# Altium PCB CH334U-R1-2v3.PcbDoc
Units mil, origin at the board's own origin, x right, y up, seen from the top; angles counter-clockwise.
Board outline 3110.24 x 866.14 mil, 2 copper layers (Top Layer, Bottom Layer); 19 components, 20 nets, 108 pads, 280 vias.
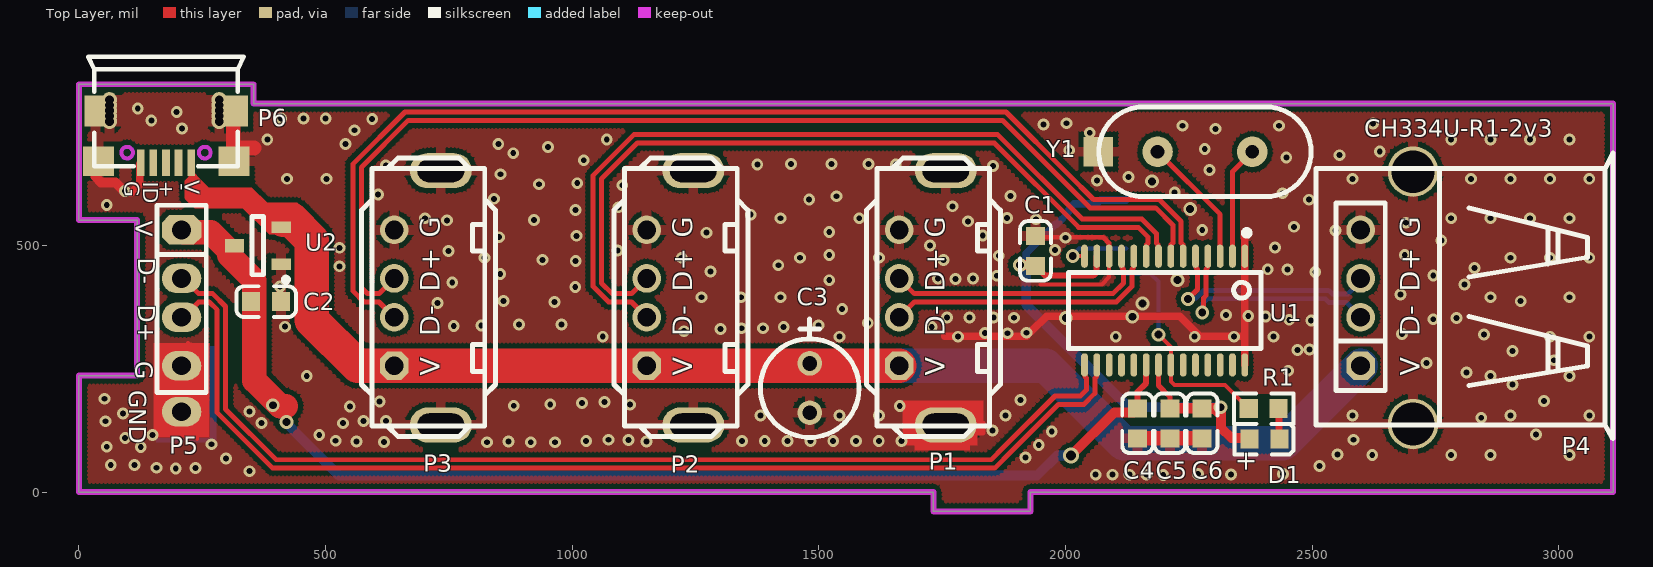
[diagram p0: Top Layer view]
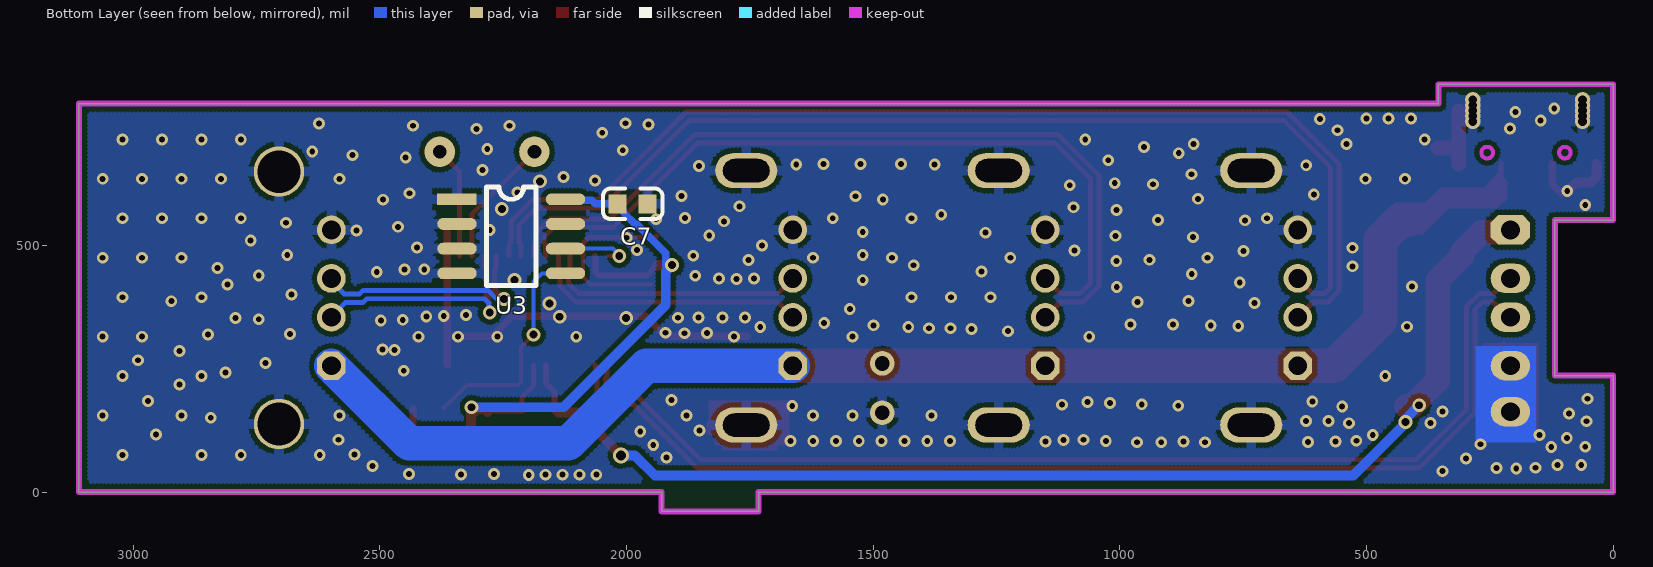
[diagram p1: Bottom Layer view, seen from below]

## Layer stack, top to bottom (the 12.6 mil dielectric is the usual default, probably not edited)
Top Solder: solder mask 0.4, Solder Resist, Dk 3.5
Top Layer: signal copper 1.4
Dielectric 1: dielectric 12.6, FR-4, Dk 4.8
Bottom Layer: signal copper 1.4
Bottom Solder: solder mask 0.4, Solder Resist, Dk 3.5

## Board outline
0,0 0,236.22 118.11,236.22 118.11,551.18 0,551.18 0,826.77 354.33,826.77 354.33,787.4 3110.24,787.4 3110.24,0 1929.13,0 1929.13,-39.37 1732.28,-39.37 1732.28,0

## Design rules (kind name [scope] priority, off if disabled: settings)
Clearance Clearance_1 [InPolygon] p1: gap=10 ignorepadtopadclearanceinfootprint=FALSE
Clearance [All] p2: gap=6 ignorepadtopadclearanceinfootprint=FALSE except(8: Arc-Via Track-Via SMDPad-Via THPad-Via Via-Via Via-Fill Via-Poly Via-Region Via-Hole)
ComponentClearance [All] p1 off: gap=10 collisioncheckmode=3 verticalgap=10 showdistances=FALSE
DiffPairsRouting [All] p1: maxlimit=10 minlimit=7 mostfreqgap=8 toplayer_minwidth=6 toplayer_maxwidth=15 toplayer_prefwidth=8 bottomlayer_minwidth=6 bottomlayer_maxwidth=15 bottomlayer_prefwidth=8 maxuncoupledlength=500
MinimumSolderMaskSliver [All] p1 off: minsoldermaskwidth=10
PolygonConnect PolygonConnect_1 [IsVia] p1: connectstyle=Direct reliefconductorwidth=10 reliefentries=4 polygonreliefangle="90 Angle" airgapwidth=10
PolygonConnect [All] p2: connectstyle=Relief reliefconductorwidth=20 reliefentries=4 polygonreliefangle="90 Angle" airgapwidth=10
RoutingVias [All] p1: holewidth=16 width=28 viastyle="Through Hole" minholewidth=12 minwidth=24 maxholewidth=28 maxwidth=50
SilkToSilkClearance [All] p1 off: silktosilkclearance=10
SilkToSolderMaskClearance [IsPad] p1 off: minsilkscreentomaskgap=10 clearancetoexposedcopper=TRUE
SolderMaskExpansion [All] p1: expansion=4 istentingtop=FALSE
Width [All] p1: maxlimit=100 minlimit=6 preferedwidth=10
25 further rules are at their usual default settings.

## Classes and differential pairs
differential pair UD: +UD_p -UD_n
differential pair UD4: +UD4_p -UD4_n
differential pair UD3: +UD3_p -UD3_n
differential pair UD2: +UD2_p -UD2_n
differential pair UD1: +UD1_p -UD1_n

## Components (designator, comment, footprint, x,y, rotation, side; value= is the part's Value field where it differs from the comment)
C1 "1uF" 0603_C 1939.33,458.56 r90 top
C2 "10uF" 0603_C 349.31,386.02 r0 top
C3 "220uF" CD0.1 1481.53,260.82 r270 top
C4 "1uF" 0603_C 2146.15,169.64 r270 top
C5 "0.1uF" 0603_C 2211.63,169.64 r270 top
C6 "10uF" 0603_C 2277.11,169.64 r270 top
C7 "NC(1uF)" 0603_C 2017.91,584.37 r180 bottom
D1 "LED" 0603+ 2372.9,107.41 r0 top
P1 "USB" USB2.0-A-F-TH_4P-V_13.7mm 1662.83,255.91 r180 top
P2 "USB" USB2.0-A-F-TH_4P-V_13.7mm 1151.02,255.91 r180 top
P3 "USB" USB2.0-A-F-TH_4P-V_13.7mm 639.21,255.91 r180 top
P4 "USB" USBAF#1 2598.25,255.91 r90 top
P5 "USB" USBAF#2 208.21,531.5 r270 top
P6 "PowerSupply" USBMICROB-02-GXPX-A1T2 227.66,667.45 r180 top
R1 "1K" 0603_R 2401.83,169.06 r0 top
U1 "CH334U" QSOP28 2363.63,478.14 r180 top
U2 "CH213K" SOT-23-3 409.9,462.15 r90 top
U3 "NC(24C02)" SOIC-8_150mil 2343.8,593.5 r270 bottom
Y1 "12M" XT_AT49 2186.69,689.86 r270 top

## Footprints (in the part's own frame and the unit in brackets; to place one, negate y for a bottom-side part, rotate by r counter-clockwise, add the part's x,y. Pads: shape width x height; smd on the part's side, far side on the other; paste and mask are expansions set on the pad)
0603+ [mm]
  rect 0.93x0.98 smd: 1(0,0) 2(1.54,0)
  silkscreen extent -0.76,-0.79 2.27,0.79
0603_C [mm]
  rect 0.93x0.98 smd: 1(0,0) 2(1.54,0)
  silkscreen extent -0.76,-0.79 2.31,0.79
0603_R [mm]
  rect 0.93x0.98 smd: 1(-0.77,0) 2(0.77,0)
  silkscreen extent -1.53,-0.79 1.54,0.79
CD0.1 [mil]
  round 50 hole 30: 1(0,0) 2(100,0)
  silkscreen extent -90,-100 150,100
QSOP28 [mm]
  oval 0.35x1.2 smd mask+0.051: 1(0,0) 2(0.635,0) 3(1.27,0) 4(1.905,0) 5(2.54,0) 6(3.175,0) 7(3.81,0) 8(4.445,0) 9(5.08,0) 10(5.715,0) 11(6.35,0) 12(6.985,0) 13(7.62,0) 14(8.255,0) 15(8.255,5.6) 16(7.62,5.6) 17(6.985,5.6) 18(6.35,5.6) 19(5.715,5.6) 20(5.08,5.6) 21(4.445,5.6) 22(3.81,5.6) 23(3.175,5.6) 24(2.54,5.6) 25(1.905,5.6) 26(1.27,5.6) 27(0.635,5.6) 28(0,5.6)
  silkscreen extent -0.82,-1.35 9.08,4.75
SOIC-8_150mil [mil]
  rect 24x80 smd: 1(0,0)
  oval 24x80 smd: 2(50,0) 3(100,0) 4(150,0) 5(150,220) 6(100,220) 7(50,220) 8(0,220)
  silkscreen extent -25,60 175,160
SOT-23-3 [mm] "SOT-23-3"
  rect 0.6x1 smd: 1(0,0) 2(1.9,0)
  rect 0.7x1 smd: 3(0.95,2.4)
  silkscreen extent -0.93,-0.38 2.45,1.49
USB2.0-A-F-TH_4P-V_13.7mm [mm]
  oval 3.2x1.8 hole 1.2 slot 2.4 at 0 deg: 0(-2.4,3.05) 0(-2.4,-10.05)
  oct 1.473x1.473 hole 0.965: 1(0,0)
  round 1.473 hole 0.965: 2(0,-2.5) 3(0,-4.5) 4(0,-7)
  silkscreen extent -5.21,-10.71 1.69,3.65
USBAF#1 [mm]
  round 2.6 hole 2.2: 0(-3,-2.7) 0(10,-2.7)
  oct 1.473x1.473 hole 0.965: 1(0,0)
  round 1.473 hole 0.965: 2(2.5,0) 3(4.5,0) 4(7,0)
  silkscreen extent -3.75,-12.99 10.95,2.29
USBAF#2 [mm]
  oct 1.524x2.032 hole 0.965: 1(0,0)
  oval 1.524x2.032 hole 0.965: 2(2.5,0) 3(4.5,0) 4(7,0)
  silkscreen extent -1.27,-1.27 8.38,1.27
USBMICROB-02-GXPX-A1T2 [mm]
  rect 1.6x1.5 smd: 0(-2.203,-0.083) 0(4.769,-0.083)
  rect 1.5x1.6 smd: 0(-2.167,-2.675)
  round 0.8 hole 0.45: 0(-1.442,-2.134) 0(-1.442,-3.243) 0(-1.442,-2.966) 0(-1.442,-2.689) 0(-1.442,-2.411) 0(4.208,-2.689) 0(4.208,-2.411) 0(4.208,-2.134) 0(4.208,-3.243) 0(4.208,-2.966)
  rect 1.1x1.6 smd: 0(4.933,-2.675)
  rect 0.4x1.35 smd mask+0.051: 1(0,0) 2(0.65,0) 3(1.3,0) 4(1.95,0) 5(2.6,0)
  Keep-Out Layer circle w0.203: c3.3,-0.525 r0.3
  Keep-Out Layer circle w0.203: c-0.7,-0.525 r0.3
  silkscreen extent -2.7,-5.46 5.3,0.17
XT_AT49 [mil]
  rect 60x60 smd: 0(0.03,-119.99)
  round 62 hole 28: 1(0,0) 2(0,192.13)
  silkscreen extent -91,-119 91,311

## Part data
C1 C2 C3 C4 C5 C6 C7: library part CAP, "Capacitor"
D1: "Typical INFRARED GaAs LED"
P1 P2 P3 P4 P5: "USB Port"
P6: library part MicroUSB, "MicroUSB Port"
R1: library part RES
U1: "4 ports High-Speed USB MTT Hub with over current detect & power control"
U2: "Ideal Diode 5V*1A"
U3: library part 24C01
Y1: library part XTAL, "Crystal Oscillator"

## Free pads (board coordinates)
  oval 80x60 hole 38: ""(208.21,162.81)

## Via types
v1: diameter 24, hole 12, Top Layer to Bottom Layer, tented both sides, 265 vias
v2: diameter 28, hole 16, Top Layer to Bottom Layer, tented both sides, 14 vias
v3: diameter 32, hole 20, Top Layer to Bottom Layer, tented both sides, 1 vias

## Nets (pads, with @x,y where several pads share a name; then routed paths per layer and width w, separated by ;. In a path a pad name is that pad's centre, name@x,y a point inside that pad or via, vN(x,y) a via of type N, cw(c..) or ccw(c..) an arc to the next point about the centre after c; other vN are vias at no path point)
3V3: C1.1 C5.1 C6.1 C7.1 D1.1 U1.13 U1.21 U3.8 | length 1479.1
  Top Layer w10: U1.21 2188.63,216.02 2211.63,193.02 C5.1
  Top Layer w12: C1.1 1959.24,438.65 2056.26,438.65 2063.29,445.68 2063.29,477.8 U1.13
  Top Layer w20: v2(1907.71,460.4) 1937.5,460.4 C1.1 ; C6.1 C5.1 2212.82,170.83 2312.93,170.83 v2(2314.13,172.03) ; C6.1@2282.24,162.58 2282.24,164.22 2286.4,168.38 2302.53,168.38 2315.66,155.26 ; v2@2313.15,170.83 2315.66,168.33 2315.66,155.26 ; D1.1 2371.07,109.24 2336.31,109.24 2315.66,129.89 2315.66,155.26
  Bottom Layer w10: C7.1@2016.85,583.32 C7.1
  Bottom Layer w15: v2(1907.71,460.4) 1907.71,463.92 v2@1910.19,466.4 ; 1920.6,447.51 1920.6,484.38 1979.23,543.01 1982.39,543.01 2007.1,567.72 2007.1,573.57 C7.1@2016.85,583.32 ; C7.1 2063.35,584.37 2070.76,591.78 2122.08,591.78 U3.8
  Bottom Layer w20: v2(1907.71,460.4) 1920.6,447.51 1920.6,379.07 2127.64,172.03 v2(2314.13,172.03)
5V: C2.1 C4.1 P5.1 U1.20 U2.3 | length 2482
  Top Layer w12: C4.1 2146.15,170.45 2146.15,203.34 2163.63,220.82 U1.20
  Top Layer w20: v2(420.75,142.21) 421.85,143.31 421.85,169.48 422.95,170.59 ; v3(2011.47,73.96) 2098.85,161.34 2137.84,161.34 C4.1
  Top Layer w50: P5.1 212.86,526.85 267.14,526.85 304.93,489.07 304.93,479.82 355.63,429.12 355.63,226.31 407.93,174.01 419.54,174.01
  Bottom Layer w20: v2(393.17,176.02) 420.75,148.44 v2(420.75,142.21) 420.75,139.49 526.89,33.35 1942.64,33.35 1983.25,73.96 v3(2011.47,73.96)
GND: C1.2 C2.2 C3.2 C4.2 C5.2 C6.2 C7.2 P1.0 P1.4 P2.0 P2.4 P3.0 P3.4 P4.0 P4.4 P5.4 P6.0 P6.5 pad. U1.1 U1.12 U1.28 U2.1 U3.1 U3.2 U3.3 U3.4 U3.7 Y1.0 | length 2598.1
  Top Layer w8: 220.81,208.41 220.81,302.53 ; 222,112.53 222,206.65 ; 225,112.53 225,206.65 ; 227.09,204.87 227.09,299 ; 230,111.08 230,205.21 ; 233,204.17 233,298.3 ; 234,111.08 234,205.21 ; 240,107.99 240,295.21 ; 1834.11,119.74 1834.11,140.29 ; 1949.47,421.2 2073.92,421.2 2088.63,435.91 U1.12
  Top Layer w10: C1.2 1941.99,516.54 1998.9,516.54 v1(1999.92,515.51) ; v1@1999.92,516.54 2076.28,516.54 2087.91,504.91 2087.91,478.87 U1.12
  Top Layer w15: 104.84,605.5 123.71,624.36 P6.5@123.71,665.85 ; 1755.16,316.05 1837.22,316.05 1882.4,316.05 v1@1921.37,316.05 ; v1@1921.37,318.73 1921.37,320.45 1925.53,324.61 1929.93,324.61 1961.78,356.46 2231.88,356.46 2272.29,316.05 2363.63,316.05 ; U1.28 2363.63,316.05 ; 2363.63,525.85 U1.1 2363.63,356.8 2363.63,316.05
  Top Layer w20: P6.0@33.46,665 33.46,639.41 45.12,627.76 74.35,627.76 91.94,610.17 v1(93.02,610.17)
  Top Layer w30: P6.0@312.99,665 P6.0@312.99,682.72 ; P6.0@312.99,772.76 P6.0@312.99,682.72 ; 354.76,697.24 327.52,697.24 P6.0@312.99,682.72 ; C4.2 C5.2 C6.2
  other v1: 2061.33,35.21 2095.56,35.21 2129.78,35.21 2164,35.21 2198.23,34.79 2268.68,36.44 2335.68,35.87 2441,36.54 345.77,42.29 196.36,47.86 157.58,49.29 236.59,48.81 2514.7,52.91 64.67,55.04 112.56,54.56 298,68.06 1919.06,69.76 2622,75 2782,75 2862,75 3022,75 2551.51,75.81 125.49,91.43 56.53,91.91 1945.85,95.33 269.09,96.97 618.87,101.5 827.57,100.97 916.07,100.97 965.42,100.97 563.05,102.8 870.97,102.68 1150.93,102.68 1344.12,103.19 1390.38,103.19 1436.63,103.19 1482.89,103.19 1529.14,103.19 1575.4,103.19 1621.65,103.19 1667.91,103.19 520.64,104.1 1028.39,103.53 1114.34,105.23 1073.49,106.08 2584.23,106.08 93.89,109.63 149.43,115.38 487.31,115.35 2953.66,116.98 1972.29,122.48 1852.19,124.57 370.18,139.83 535.35,139.58 54.14,143.63 576.89,143.91 622.77,143.91 2842.89,150.73 1382,155 1542,155 1622,155 1878.22,155.1 2582,155 2902,155 3062,155 89.58,159.43 345.61,163.53 549.2,173.34 1664.05,174.13 881.63,174.96 1117.55,177.16 955.63,177.89 1020.11,180.82 1065.53,182.28 609.78,183.72 2970.04,184.47 1909.19,186.51 51.74,189.12 2906.47,218.22 462,235 2862,235 3022,235 2813.04,242.58 2451.62,245.94 2732.05,261.79 2990.27,267.24 2906.47,285.71 2470.56,288.06 2494.58,288.9 1062,315 1542,315 1782,315 2102,315 2262,315 2342,315 2422,315 2982,315 3062,315 2848.67,319.45 2681.97,320.55 1837.22,322.36 1882.4,321.92 1921.37,322.89 1226.76,326.1 1300.83,330.59 1343.48,332.09 1386.87,332.09 1428.77,334.33 1729.02,334.29 417.75,335.28 760.01,336.88 815.69,337.61 1499.1,338.07 891.89,339.81 978.34,339.81 1599.31,342.91 2498.14,347.64 2453.7,349.18 2745.54,350.41 1895.47,353.41 2792.74,353.2 1759.58,353.55 1805.52,353.88 1854.11,354.21 2405.89,356.11 2370.55,356.8 2325.61,359.04 1547.41,370.82 727.04,383.04 964.42,385.23 861.12,387.43 2922.84,386.94 1262,395 1342,395 1422,395 2862,395 3022,395 2679.08,400.49 1006.25,415.39 407.69,416.39 2809.11,420.69 756.97,424.97 1521.18,429.51 1776.76,432.22 1741.73,433.21 1812.79,433.21 1860.72,438.5 2745.54,439.02 854.15,442.07 2506.38,445.9 1280.14,447.3 2449.96,450.97 2410.03,451.6 2829.34,454.43 528.28,457.62 1417.86,459.82 1007.16,468.13 1752.63,470.43 939.67,470.84 822,475 1222,475 1462,475 1622,475 2902,475 2982,475 3062,475 1864.76,479.09 2687.75,480.44 1521.18,480.68 749.2,488.72 1092.03,489.51 1978.53,490.41 528.28,495.19 2424.77,495.93 1725.48,499.88 2761.91,510.3 851.82,516.71 1009,519.49 1832.29,520.21 1272.17,525.84 1521.18,527.32 2547.29,530.47 2277.37,531.17 2463.48,537.76 2690.64,545.94 1802.57,548.85 746.09,550.91 922.56,551.69 1940.47,553.02 702,555 1422,555 1582,555 1881.66,555.45 2782,555 2862,555 2942,555 3022,555 1362.09,562.26 1006.71,571.47 1093.71,577.24 1770.67,579.29 56.52,582.14 1480.46,592.99 2493.44,592.7 841.71,594.45 1535.62,599.64 1888.37,600.38 606.78,603.49 2439.65,605.79 2221.41,607.65 1101.53,621.94 932.67,623.99 1010.25,626.12 2064.1,631.9 422,635 502,635 2582,635 2822,635 2902,635 2982,635 3062,635 2127.52,638.74 854.93,644.21 2291.67,653.04 1852.78,660.76 622.24,662.42 1375.3,663.89 1655.97,663.89 1443.81,664.72 1525.54,664.72 1600.66,664.72 1023.41,672.66 2447.74,677.92 2555.52,682.93 880.58,686.96 2637.09,690.68 2007.76,692.99 2282.34,695.33 951.33,699.4 540.34,705.78 850.26,705.62 382,715 1070.19,714.85 2782,715 2862,715 2942,715 3022,715 2049.23,728.4 559.03,733.42 2304.1,736.36 209.17,737.14 2237.57,742.58 2432.81,742.58 1955.73,745.02 2623.79,747.43 2001.86,747.7 146.87,753.14 594.56,756.21 409.91,757.18 455.11,757.18 500.31,757.18 198.29,770.28 119.32,777.75
  other v2: 2000.78,352.78 2135.57,355.3 2156.25,382.45 2227.08,429.89 2252.85,574.13 2175.55,629.96
NetD1_2: D1.2 R1.2 | length 62.2
  Top Layer w15: R1.2 2432.84,168.37 2432.84,108.1 D1.2
NetU1_2: U1.2 Y1.2 | length 228.4
  Top Layer w10: U1.2 2338.63,649.68 Y1.2
NetU1_3: U1.3 Y1.1 | length 264.3
  Top Layer w10: Y1.1 2313.63,562.92 U1.3
RST: U1.17
SCL: U1.14 U3.6 | length 140.6
  Top Layer w8: v2(2014.88,478.5) 2038.27,478.5 U1.14
  Bottom Layer w8: v2(2014.88,478.5) 2014.88,481.18 2027.2,493.5 U3.6
SDA: R1.1 U1.22 U3.5 | length 466
  Top Layer w8: v2(2188.34,319.06) 2213.63,293.77 U1.22 2213.63,223.9 2220.64,216.89 2323.68,216.89 2356.23,184.35 2357.21,184.35 2371.52,170.04 R1.1
  Bottom Layer w8: U3.5 2171.64,443.5 2188.34,426.8 v2(2188.34,319.06)
UD1_n: P1.2 U1.10 | length 560.8
  Top Layer w10: P1.2 1693.7,385.2 2103.23,385.2 2134.63,416.6 2134.63,451.45 2137.91,454.73 2137.91,477.42 U1.10
UD1_p: P1.3 U1.11 | length 532.6
  Top Layer w10: P1.3 1693.7,402.2 2096.19,402.2 2117.63,423.64 2117.63,451.45 2114.35,454.73 2114.35,477.42 U1.11
UD2_n: P2.2 U1.8 | length 1666.8
  Top Layer w10: P2.2 1120.15,385.2 1073.88,385.2 1042.46,416.62 1042.46,642.09 1125.07,724.7 1862.77,724.7 2033.79,553.67 2154.76,553.67 2184.63,523.81 2184.63,504.83 2187.91,501.55 2187.91,478.87 U1.8
UD2_p: P2.3 U1.9 | length 1582.3
  Top Layer w10: P2.3 1120.15,402.2 1080.92,402.2 1059.46,423.67 1059.46,635.05 1132.11,707.7 1855.72,707.7 2026.75,536.67 2147.72,536.67 2167.63,516.76 2167.63,504.83 2164.35,501.55 2164.35,478.87 U1.9
UD3_n: P3.2 U1.6 | length 2249.5
  Top Layer w10: P3.2 608.34,385.2 578.03,385.2 555.84,407.39 555.84,665.25 660.99,770.4 1879.53,770.4 2003.96,645.97 2056.78,593.15 2189.98,593.15 2234.63,548.49 2234.63,504.83 2237.91,501.55 2237.91,478.87 U1.6
UD3_p: P3.3 U1.7 | length 2165
  Top Layer w10: P3.3 608.34,402.2 585.07,402.2 572.84,414.43 572.84,658.21 668.04,753.4 1872.49,753.4 1986.96,638.93 2049.74,576.15 2182.94,576.15 2217.63,541.45 2217.63,504.83 2214.35,501.55 2214.35,478.87 U1.7
UD4_n: P4.2 U1.4 | length 477
  Top Layer w10: v2@2276.3,364.89 2279.74,368.34 2279.74,393.21 2284.63,398.09 2284.63,451.45 2287.91,454.73 2287.91,477.42 U1.4
  Bottom Layer w10: v2@2276.3,364.89 2279.13,367.72 2279.13,383.07 2287.92,391.87 2526.78,391.87 2533.98,384.66 2569.58,384.66 2598.25,355.99 P4.2
  other v2: 2277.3,363.89
UD4_p: P4.3 U1.5 | length 471.1
  Top Layer w10: v2@2249.3,392.35 2267.63,410.68 2267.63,451.45 2264.35,454.73 2264.35,477.42 U1.5
  Bottom Layer w10: v2@2249.3,390.35 2252.74,393.79 2265.81,393.79 2280.88,408.87 2533.82,408.87 2541.02,401.66 2572.67,401.66 2598.25,427.24 P4.3
  other v2: 2248.3,391.35
UD_n: P5.2 U1.15 | length 2219.5
  Top Layer w10: P5.2 211.83,433.07 242.7,402.2 271.31,402.2 297.25,376.26 297.25,168.13 399.94,65.44 1849.49,65.44 1874.26,90.21 1978.67,194.63 2030.12,194.63 2042.63,207.14 2042.63,230.98 2039.35,234.26 2039.35,256.95 U1.15
UD_p: P5.3 U1.16 | length 2247.7
  Top Layer w10: P5.3 211.83,354.33 242.7,385.2 264.27,385.2 280.25,369.22 280.25,161.09 392.9,48.44 1856.53,48.44 1891.26,83.17 1985.72,177.63 2037.16,177.63 2059.63,200.1 2059.63,230.98 2062.91,234.26 2062.91,256.95 U1.16
VBUS: C3.1 P1.1 P2.1 P3.1 P4.1 P6.1 U2.2 | length 3125.2
  Top Layer w10: 247.13,591.38 252.13,591.38 ; 252.85,603.63 251.45,605.02 ; 252.85,608.63 252.85,605.02 ; 254.37,584.14 259.37,584.14 ; 267.21,605.02 262.21,605.02 ; 219.15,602.21 241.73,579.63 ; 219.15,602.21 219.15,629.22 226.76,636.83 226.76,666.54 P6.1 P6.1@227.66,646.78 ; 219.15,602.21 219.15,597.21 236.73,579.63 241.73,579.63 ; 227.66,615.85 227.66,619.83 ; 227.66,615.85 227.66,604.47 252.5,579.63 ; 227.66,615.85 238.49,605.02 ; 227.66,619.83 227.66,628.81 ; 227.66,619.83 242.47,605.02 ; 227.66,628.81 251.45,605.02 ; 227.66,628.81 P6.1@227.66,646.78 ; P6.1@227.66,646.78 234.14,640.3 ; 234.14,640.3 274.41,600.02 267.21,600.02 ; 234.14,640.3 234.14,633.09 262.21,605.02 ; 238.49,605.02 242.47,605.02 ; 238.49,605.02 252.13,591.38 ; 241.73,579.63 252.5,579.63 ; 242.47,605.02 251.45,605.02 ; 242.47,605.02 247.47,600.02 257.85,600.02 ; 251.45,605.02 252.85,605.02 ; 252.13,591.38 266.49,591.38 257.85,600.02 ; 252.13,591.38 259.37,584.14 ; 252.5,579.63 263.88,579.63 259.37,584.14 ; 252.85,605.02 262.21,605.02 ; 252.85,605.02 257.85,600.02 ; 257.85,600.02 267.21,600.02 ; 262.21,605.02 267.21,600.02
  Top Layer w70: 414.81,552.09 431.06,552.09 472.49,510.66 472.49,348.53 565.12,255.91 P3.1 P2.1 P1.1
  Bottom Layer w70: P1.1 1960.48,255.91 2117.89,98.49 2440.84,98.49 P4.1
pads on no net: P6.2 P6.3 P6.4 U1.18 U1.19 U1.23 U1.24 U1.25 U1.26 U1.27

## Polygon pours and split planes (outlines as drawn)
GND on Top Layer "GND" (hatched 90Degree grid 8 track 8, remove dead copper, pour order 0): 0,826.77 0,551.18 118.11,551.18 118.11,236.22 0,236.22 0,0 1732.28,0 1732.28,-39.37 1929.13,-39.37 1929.13,0 3110.24,0 3110.24,787.4 354.33,787.4 354.33,826.77
GND on Bottom Layer "GND" (hatched 90Degree grid 8 track 8, remove dead copper, pour order 1): 0,826.77 0,551.18 118.11,551.18 118.11,236.22 0,236.22 0,0 1732.28,0 1732.28,-39.37 1929.13,-39.37 1929.13,0 3110.24,0 3110.24,787.4 354.33,787.4 354.33,826.77

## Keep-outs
Keep-Out Layer:
  the board outline again, w12

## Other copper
Top Layer:
  rectangle net GND: 1694,84.44 1806,101.7
  rectangle net GND: 1668.7,94.34 1822.2,119.41
  rectangle net GND: 1669.7,115 1834.11,185.26
  rectangle net GND: 151.31,111.08 265.24,302.38
  region net VBUS: 219.15,597.21 240.61,575.75 332.22,575.75 385.76,522.21 442.61,522.21 451.78,531.38 449.92,533.24 456.21,539.53 456.21,572.6 442.44,586.37 381.43,586.37 350.88,616.92 220.35,616.92 219.15,615.71
Bottom Layer:
  rectangle net GND: 156.56,100.86 278.7,295.9

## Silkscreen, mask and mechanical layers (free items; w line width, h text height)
Top Overlay:
  text "CH334U-R1-2v3" at 2605.38,720.57 h35
  text "GND" at 102.23,206.83 h35 r270
Mechanical 1:
  lines w10: 0,0 0,236.22 118.11,236.22 118.11,551.18 0,551.18 0,787.4 0,826.77 354.33,826.77 354.33,787.4 3110.24,787.4 3110.24,0 1929.13,0 1929.13,-39.37 1732.28,-39.37 1732.28,0 0,0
